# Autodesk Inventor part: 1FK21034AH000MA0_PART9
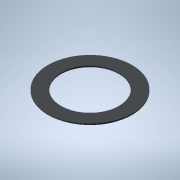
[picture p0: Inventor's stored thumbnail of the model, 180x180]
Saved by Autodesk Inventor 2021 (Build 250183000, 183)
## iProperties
Created: 2025-04
Part Number: 1FK21034AH000MA0_PART9
Material: Generic
Catalog Web Link: www.3dfindit.com
Description: -Servo synchronous motor
Document SubType Name: Modeling
Designer: psAdmin
Mass: 0.211555 g
Surface Area: 9.31012 cm^2
Volume: 0.211555 cm^3
Density: 1 g/cm^3
Appearance: PSOLRGB-212-217-219
Category: PARTsolutions
Title: 1FK21034AH000MA0_PART9
Author: Cadenas PARTsolutions
Comments: Servo synchronous motor
Sending System: PARTsolutions
Preprocessor: ST-DEVELOPER v19.3
PSOL_IDENT_0: {$CADENAS_DATA/23d-libs/siemens_ag/_cat_/ec/b7/1fk21034ah000ma0.prj},213 {VTYP=3D},{NB=1FK21034AH000
PSOL_IDENT_1: MA0_PART9},{LINA=1FK21034AH000MA0_PART9},{NN=1FK21034AH000MA0_PART9},{NOPRJ=TRUE},{DATE=19.08.2025 1
PSOL_IDENT_2: 4:01:05},{GEOMDATE=30.07.2025 02:01:02},{VERSION=},{LINEID=10},{WBVAR=},{WBNUMERIC=}  {NB=1FK21034AH
PSOL_IDENT_3: 000MA0_PART9},{LINA=1FK21034AH000MA0_PART9},{KT=DUMMY},{PREVIEW=../../../_pool_/7c/50/p_d211_xx_0093
PSOL_IDENT_4: 2j.png},{DESCSHORT=SIMOTICS S-1FK2 HD, SINAMICS S210 3AC 400V-480V, 1.01 Nm, 4500 rpm},{DESCLONG=SIM
PSOL_IDENT_5: OTICS S-1FK2 HD servo motor M0=1.27 Nm; PN = 0.48 kW at nN=4500 rpm (380-480 V); PN = 0.3 kW at nN=2
PSOL_IDENT_6: 500 rpm (200-240 V); degree of protection IP64; cylindrical shaft D14 x 30 mm; absolute encoder 22-b
PSOL_IDENT_7: it + 12-bit multiturn (encoder AM22DQC); with OCC interface; plug size M17, rotatable; SIMOTICS S-1F
PSOL_IDENT_8: K2 servomotorfor a wide range of uses in industrial environments. SIMOTICS S‑1FK2 servomotors are co
PSOL_IDENT_9: mpact synchronous motors with a high dynamic performance that set themselves apart as a result of th
PSOL_IDENT_10: eir high power density, degree of protection and overload capability. The motors are available in tw
PSOL_IDENT_11: o variants: as High Dynamic variant (highest dynamic performance as a result of the low intrinsic mo
PSOL_IDENT_12: ment of inertia for applications demanding a high dynamic performance with low moved masses) - and a
PSOL_IDENT_13: s Compact variant (precise and stable closed-loop control for medium up to large moved masses as a r
PSOL_IDENT_14: esult of a medium intrinsic moment of inertia). SIMOTICSS‑1FK2 servomotors fully exploit their stren
PSOL_IDENT_15: gths in a system with the SINAMICSS210 frequency converter and simple connection using the one cable
PSOL_IDENT_16: connection (OCC). Advantages include the short control and positioning times, fast and precise corr
PSOL_IDENT_17: ection of disturbing quantities as well as stable control with a high dynamic performance. The servo
PSOL_IDENT_18: motors can be configured to address a wide range of requirements. For example with and without hold
PSOL_IDENT_19: ing brake, IP64 or IP65 degree of protection, singleturn or multiturn absolute encoders - to name ju
PSOL_IDENT_20: st a few. Further, the servomotors are available in different shaft heights extending from 20 to 100
PSOL_IDENT_21: . A shaft sealing ring is available to achieve an IP65 degree of protection and for subsequent mount
PSOL_IDENT_22: ing at the motor or as spare part. SIMOTICS - the optimum motor for each and every motion control ap
PSOL_IDENT_23: plication.},{INTNO=4034106444822},{SUPPLIERALTNO=1FK2103-4AH00-0MA0},{MANUID=1FK21034AH000MA0},{MANU
PSOL_IDENT_24: NAME=Siemens},{MANUTYPEDESC=SYNCHRONOUS MOTOR 1FK2 HD 1,27 NM},{AAU732=SIMOTICS},{AAO057=S-1FK2},{AA
PSOL_IDENT_25: U734=SIMOTICS S-1FK2 HD servo motor M0=1.27 Nm; PN = 0.48 kW at nN=4500 rpm (380-480 V); PN = 0.3 kW
PSOL_IDENT_26: at nN=2500 rpm (200-240 V); degree of protection IP64; cylindrical shaft D14 x 30 mm; absolute enco
PSOL_IDENT_27: der 22-bit + 12-bit multiturn (encoder AM22DQC); with OCC interface; plug size M17, rotatable;},{AAW
PSOL_IDENT_28: 338=SYNCHRONOUS MOTOR 1FK2 HD 1,27 NM},{AAO742=SIMOTICS},{AAO663=4034106444822},{NOCUPEROU=1},{PRICE
PSOL_IDENT_29: QUANTITY=1},{QUANTITYMIN=1},{QUANTITYINT=1},{CTN=85015100},{COO=RO},{AAO676=1FK2103-4AH00-0MA0},{AAO
PSOL_IDENT_30: 677=Siemens AG},{ORDERUNIT=C62},{CONTENTUNIT=C62}
NB: 1FK21034AH000MA0_PART9
NT: Servo synchronous motor
NBSYN: $MANUID._PART9
LINA: 1FK21034AH000MA0_PART9
CATALOG: SIEMENS
PREVIEW: ../../../_pool_/7c/50/p_d211_xx_00932j.png
DESCSHORT: SIMOTICS S-1FK2 HD, SINAMICS S210 3AC 400V-480V, 1.01 Nm, 4500 rpm
DESCLONG: SIMOTICS S-1FK2 HD servo motor M0=1.27 Nm; PN = 0.48 kW at nN=4500 rpm (380-480 V); PN = 0.3 kW at nN=2500 rpm (200-240 V); degree of protection IP64; cylindric
INTNO: 4034106444822
SUPPLIERALTNO: 1FK2103-4AH00-0MA0
MANUID: 1FK21034AH000MA0
MANUNAME: Siemens
MANUTYPEDESC: SYNCHRONOUS MOTOR 1FK2 HD 1,27 NM
AAU732: SIMOTICS
AAO057: S-1FK2
AAU734: SIMOTICS S-1FK2 HD servo motor M0=1.27 Nm; PN = 0.48 kW at nN=4500 rpm (380-480 V); PN = 0.3 kW at nN=2500 rpm (200-240 V); degree of protection IP64; cylindric
AAW338: SYNCHRONOUS MOTOR 1FK2 HD 1,27 NM
AAO742: SIMOTICS
AAO663: 4034106444822.0
NOCUPEROU: 1
PRICEQUANTITY: 1
QUANTITYMIN: 1
QUANTITYINT: 1
CTN: 85015100
COO: RO
ARTICLENO: 1FK21034AH000MA0_PART9
BOMINFO: 1FK21034AH000MA0_PART9
CREATOR: CADENAS GmbH
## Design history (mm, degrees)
feature "2025_04_17_15_01_37_0314"
body "Solid1"
